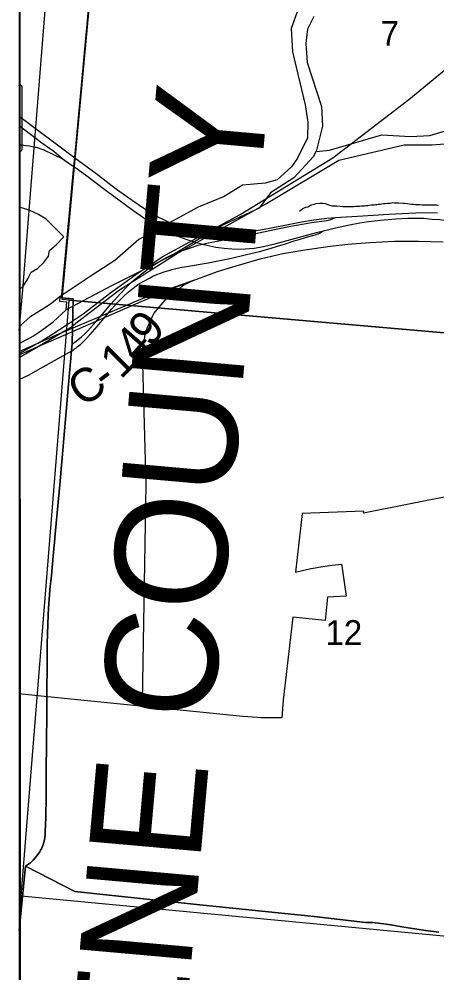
# Model space of a CAD drawing. Extents: x -1.4 to 35.4, y 0 to 22.
# Drawn here: x 24.49 to 25.196, y 14.805 to 16.414 of the extents above; entities that cross this region are included whole.
import ezdxf

# ---------------------------------------------------------------- set-up
doc = ezdxf.new("R2010")
doc.units = 0
for name, color, linetype in [('GM_X_City_Street', 7, 'Continuous'), ('GM_X_County_Road', 7, 'Continuous'), ('GM_X_County_Road_Text', 7, 'Continuous'), ('GM_X_County_Text', 7, 'Continuous'), ('GM_X_Interstate_Shield', 7, 'Continuous'), ('GM_X_Major_River', 7, 'Continuous'), ('GM_X_Minor_Lake', 7, 'Continuous'), ('GM_X_Minor_River', 7, 'Continuous'), ('GM_X_Rail_Line', 7, 'Continuous'), ('GM_X_Section', 7, 'Continuous'), ('GM_X_Section_Text', 7, 'Continuous'), ('GM_X_State_Route', 7, 'Continuous'), ('SC_Scratch1', 7, 'Continuous'), ('SH_Border', 7, 'Continuous'), ('SH_Cut_Line', 7, 'Continuous')]:
    doc.layers.add(name, color=color, linetype=linetype)

msp = doc.modelspace()

# ---------------------------------------------------------------- linework, layer by layer
at = {"layer": 'GM_X_City_Street'}
for p, q in [((24.5666, 16.1759), (24.5826, 16.1649)), ((24.5254, 15.8243), (24.5787, 15.8543))]:
    msp.add_line(p, q, dxfattribs=at)
for points in [[(24.4897, 16.2345), (24.5283, 16.2054), (24.5482, 16.1911), (24.5642, 16.1776), (24.5666, 16.1759)], [(24.4897, 15.8061), (24.5068, 15.8138), (24.5254, 15.8243)]]:
    msp.add_lwpolyline(points, dxfattribs=at)
at = {"layer": 'GM_X_County_Road'}
for points in [[(24.5798, 15.8662), (24.586, 15.8708), (24.5953, 15.8779), (24.6005, 15.8826), (24.6051, 15.8873), (24.6103, 15.893), (24.6155, 15.8987), (24.6339, 15.9199), (24.6449, 15.9329), (24.661, 15.9512), (24.6726, 15.9633), (24.6797, 15.97), (24.6842, 15.9739), (24.696, 15.9837), (24.7073, 15.992), (24.7187, 15.9998), (24.7288, 16.006), (24.7398, 16.012), (24.7478, 16.0161), (24.7547, 16.0191), (24.7642, 16.0229), (24.7774, 16.0276), (24.7922, 16.0324), (24.7994, 16.0341), (24.8097, 16.0366), (24.8384, 16.0422), (24.8762, 16.0495), (24.9212, 16.059), (24.9456, 16.0639), (24.9714, 16.0686), (24.9835, 16.0705), (24.9965, 16.0722), (25.0057, 16.0735), (25.0091, 16.0741), (25.012, 16.0748), (25.0148, 16.0755), (25.0189, 16.0769), (25.0244, 16.0791)], [(24.6898, 15.9653), (24.6906, 15.9659), (24.6991, 15.9711), (24.7109, 15.9773), (24.7159, 15.98), (24.7224, 15.983), (24.7285, 15.9854), (24.7349, 15.9877), (24.7426, 15.99), (24.7475, 15.9914), (24.7546, 15.993), (24.7618, 15.9946), (24.7723, 15.9963), (24.8089, 16.0029), (24.8484, 16.0108), (24.874, 16.0167), (24.8958, 16.0221), (24.914, 16.027), (24.9281, 16.0313), (24.9378, 16.0343), (24.9544, 16.0397), (24.9627, 16.0423), (24.9752, 16.046), (24.9898, 16.05), (24.9933, 16.0511), (24.9952, 16.0518), (24.997, 16.0527), (24.9998, 16.0543), (25.0037, 16.0568)], [(24.6299, 15.9054), (24.6461, 15.9244), (24.6559, 15.9358), (24.6659, 15.9458), (24.6741, 15.9534), (24.6824, 15.9601), (24.6898, 15.9653)], [(24.5787, 15.8543), (24.5814, 15.8559), (24.5834, 15.8574), (24.5856, 15.8589), (24.5879, 15.8607), (24.5932, 15.865), (24.5996, 15.8709), (24.6096, 15.8818), (24.6214, 15.8954), (24.6299, 15.9054)]]:
    msp.add_lwpolyline(points, dxfattribs=at)
msp.add_lwpolyline([(24.4897, 14.8983), (24.4897, 13.9389), (25.4028, 13.8449), (25.498, 14.8392), (24.493, 14.9341)], close=True, dxfattribs=at)
at = {"layer": 'GM_X_County_Text'}
msp.add_lwpolyline([(24.4897, 16.8794), (24.4897, 15.8886), (24.4962, 15.9571), (24.5508, 16.6406), (24.5643, 16.8095), (24.5679, 16.8544), (24.5697, 16.8763), (24.5697, 16.8774), (24.5713, 16.8967), (24.5728, 16.9155), (24.5693, 16.9139)], close=True, dxfattribs=at)
msp.add_lwpolyline([(25.2985, 15.6255), (25.0715, 15.5802), (25.0719, 15.5835), (24.968, 15.5798), (24.9568, 15.481), (24.9828, 15.4872), (24.983, 15.4872), (25.0027, 15.4905), (25.0029, 15.4905), (25.0187, 15.4924), (25.0187, 15.4924), (25.0344, 15.4941), (25.0348, 15.4913), (25.0425, 15.4402), (25.0109, 15.4383), (25.0068, 15.3994), (24.9524, 15.405), (24.9356, 15.2647), (24.9336, 15.2347), (24.8981, 15.2351), (24.8923, 15.2355), (24.8679, 15.2374), (24.5271, 15.2714), (24.4897, 15.2752), (24.4897, 14.0665)], dxfattribs=at)
at = {"layer": 'GM_X_Interstate_Shield'}
msp.add_line((24.4897, 16.3021), (24.4897, 16.1897), dxfattribs=at)
msp.add_lwpolyline([(24.4947, 16.1944), (24.4947, 16.1944), (24.4947, 16.1943), (24.4947, 16.2992)], dxfattribs=at)
for centre, major_axis, start_param, end_param in [((24.3773, 16.5669), (0.3495, 0), 5.039656, 5.042369), ((24.4911, 16.2995), (0.00367, 0), 6.197627, 7.989034), ((24.4939, 16.1867), (0.00568, 0), 1.883976, 2.403227), ((24.4908, 16.1939), (0.00393, 0), 5.054544, 6.418171)]:
    msp.add_ellipse(centre, major_axis=major_axis, ratio=0.8, start_param=start_param, end_param=end_param, dxfattribs=at)
at = {"layer": 'GM_X_Major_River'}
for p, q in [((24.5705, 15.9365), (24.5587, 15.9373)), ((24.5694, 15.9235), (24.5705, 15.9365))]:
    msp.add_line(p, q, dxfattribs=at)
for points in [[(24.9613, 16.4307), (24.9495, 16.3983), (24.9515, 16.3585), (24.9731, 16.2695), (24.9773, 16.2402), (24.977, 16.2136), (24.9602, 16.1792), (24.95, 16.1646), (24.9255, 16.1429), (24.9056, 16.137), (24.8672, 16.1335), (24.8364, 16.1149), (24.792, 16.0964), (24.692, 16.0422), (24.6516, 16.0065), (24.6131, 15.9817), (24.5593, 15.946)], [(24.9876, 16.4182), (24.9772, 16.3972), (24.9739, 16.373), (24.9765, 16.3407), (25.0007, 16.2665), (25.0025, 16.2334), (24.9924, 16.1927), (24.9872, 16.1822), (24.954, 16.1463), (24.9143, 16.1208), (24.8951, 16.0948), (24.8298, 16.0643), (24.7478, 16.0149), (24.6456, 15.9641), (24.5695, 15.9235)], [(24.5593, 15.946), (24.5426, 15.933), (24.5287, 15.9237), (24.5187, 15.9178), (24.5076, 15.9111), (24.4929, 15.8977), (24.4897, 15.8944)], [(24.5587, 15.9373), (24.5593, 15.946)], [(24.4897, 15.8664), (24.4909, 15.8669), (24.5028, 15.8732), (24.514, 15.8798), (24.524, 15.8865), (24.5343, 15.8936), (24.5474, 15.9029), (24.5694, 15.9235)]]:
    msp.add_lwpolyline(points, dxfattribs=at)
at = {"layer": 'GM_X_Minor_Lake'}
for points in [[(24.5652, 16.0464), (24.5356, 16.0765), (24.5228, 16.0843), (24.5077, 16.091), (24.4979, 16.0942), (24.4897, 16.0969)], [(24.4897, 15.9573), (24.497, 15.9641), (24.5044, 15.9758), (24.5103, 15.9871), (24.521, 15.9934), (24.5315, 16.0035), (24.5396, 16.0137), (24.5413, 16.0235), (24.5525, 16.0332), (24.5652, 16.0464)]]:
    msp.add_lwpolyline(points, dxfattribs=at)
at = {"layer": 'GM_X_Minor_River'}
for points in [[(24.9913, 16.1906), (25.0139, 16.1929), (25.1025, 16.2185), (25.151, 16.216), (25.1836, 16.2176), (25.2172, 16.2275)], [(24.9635, 16.0897), (24.9689, 16.0942), (24.9742, 16.0964), (24.9773, 16.0971), (24.983, 16.1004), (24.988, 16.1019), (24.9914, 16.1026), (24.9979, 16.1032), (25.0028, 16.1031), (25.0066, 16.1027), (25.0111, 16.1011), (25.0149, 16.0999), (25.0183, 16.0991), (25.0202, 16.0991), (25.0266, 16.0986), (25.0323, 16.0981), (25.0369, 16.098), (25.0399, 16.098), (25.0422, 16.0976), (25.0441, 16.0975), (25.0464, 16.0975), (25.049, 16.0975), (25.0524, 16.0978), (25.0551, 16.0977), (25.0581, 16.0981), (25.0616, 16.0984), (25.065, 16.0983), (25.068, 16.0987), (25.0707, 16.099), (25.073, 16.099), (25.0756, 16.0993), (25.0787, 16.0996), (25.0817, 16.1), (25.0851, 16.1003), (25.0874, 16.1006), (25.0897, 16.1006), (25.092, 16.1009), (25.0939, 16.1013), (25.0962, 16.1016), (25.0981, 16.1016), (25.1003, 16.1019), (25.1026, 16.1023), (25.1053, 16.1026), (25.1083, 16.103), (25.1118, 16.1033), (25.1159, 16.1036), (25.1186, 16.1039), (25.1213, 16.1043), (25.1239, 16.1042), (25.1266, 16.1042), (25.1285, 16.1041), (25.1311, 16.1041), (25.1383, 16.1032), (25.141, 16.1032), (25.1452, 16.1027), (25.1486, 16.1023), (25.1524, 16.1019), (25.1561, 16.1018), (25.1596, 16.1014), (25.1633, 16.1009), (25.1668, 16.1009), (25.1706, 16.1008), (25.1744, 16.1007), (25.1785, 16.1007), (25.1827, 16.1006), (25.1869, 16.1005), (25.1918, 16.1005), (25.1952, 16.1004), (25.1983, 16.1)]]:
    msp.add_lwpolyline(points, dxfattribs=at)
at = {"layer": 'GM_X_Rail_Line'}
for p, q in [((24.5608, 15.8846), (24.5702, 15.8901)), ((24.5608, 15.8846), (24.5701, 15.8886)), ((24.5216, 15.8671), (24.5608, 15.8846)), ((24.5216, 15.8671), (24.5284, 15.871)), ((24.4897, 15.8497), (24.5216, 15.8671)), ((24.4897, 15.8529), (24.5216, 15.8671)), ((24.4897, 15.8427), (24.5234, 15.8625))]:
    msp.add_line(p, q, dxfattribs=at)
for points in [[(24.5708, 15.8987), (24.5978, 15.9168), (24.6424, 15.9512), (24.687, 15.983), (24.7317, 16.013), (24.863, 16.0843), (25.02, 16.1797), (25.1479, 16.2785), (25.2655, 16.3747), (25.3419, 16.4375), (25.6578, 16.8086), (26.0527, 17.3064), (27.8807, 19.1678), (28.3781, 19.6365)], [(24.5702, 15.8901), (24.5764, 15.8937), (24.5853, 15.9005), (24.5864, 15.9014), (24.6592, 15.9569), (24.7558, 16.0181), (24.9077, 16.1029), (25.0299, 16.1759), (25.1403, 16.2016), (25.1876, 16.2016), (25.2566, 16.2075), (25.3099, 16.2293), (26.5579, 16.8687), (27.4944, 17.3029), (28.0569, 17.523)], [(24.5801, 15.8868), (24.6962, 15.9376), (24.7642, 15.9656), (24.825, 15.9878), (24.8563, 15.9979), (24.8968, 16.0093), (24.9353, 16.0182), (24.9725, 16.0248), (25.0153, 16.0311), (25.0452, 16.0341), (25.0824, 16.0372), (25.1237, 16.039), (25.1642, 16.0393), (25.2063, 16.0379)], [(24.5701, 15.8886), (24.6991, 15.9428), (24.786, 15.9742)], [(24.698, 15.2627), (24.7042, 15.6287), (24.699, 15.8323), (24.7001, 15.8602), (24.7031, 15.8861), (24.7176, 15.9171), (24.7393, 15.9429), (24.7682, 15.9657), (24.786, 15.9742)], [(24.4897, 15.8473), (24.5311, 15.8652), (24.5658, 15.8805), (24.5728, 15.8836), (24.5801, 15.8868)], [(24.5284, 15.871), (24.5453, 15.882), (24.5708, 15.8987)], [(24.5234, 15.8625), (24.5493, 15.8778), (24.5608, 15.8846)]]:
    msp.add_lwpolyline(points, dxfattribs=at)
at = {"layer": 'GM_X_Section'}
for points in [[(25.6685, 16.8528), (25.5769, 15.8524), (24.5744, 15.9398), (24.5624, 15.9411), (24.6573, 16.9582)], [(24.5744, 15.9398), (25.5769, 15.8524), (25.5939, 15.8506), (25.498, 14.8392), (24.493, 14.9341)]]:
    msp.add_lwpolyline(points, close=True, dxfattribs=at)
at = {"layer": 'GM_X_State_Route'}
msp.add_line((24.4897, 16.2502), (24.584, 16.1801), dxfattribs=at)
for points in [[(24.4897, 16.202), (24.4934, 16.202), (24.5068, 16.2003), (24.5174, 16.1978)], [(24.5174, 16.1978), (24.5185, 16.1976), (24.5314, 16.1935), (24.5642, 16.1776)], [(24.584, 16.1801), (24.6193, 16.1538), (24.6545, 16.1272), (24.6808, 16.1083), (24.7002, 16.095), (24.7139, 16.0863), (24.7253, 16.0799), (24.7359, 16.0745), (24.7468, 16.0698), (24.7584, 16.0654), (24.7709, 16.0614), (24.7836, 16.0581), (24.796, 16.0554), (24.8089, 16.0533), (24.8207, 16.0522), (24.8349, 16.0516), (24.849, 16.052), (24.857, 16.0526), (24.8635, 16.0532), (24.8795, 16.0553), (24.901, 16.059), (24.9357, 16.0658), (24.9668, 16.0717), (24.9877, 16.075), (25.0098, 16.0778), (25.0244, 16.0791), (25.0327, 16.0799), (25.0612, 16.0817), (25.1145, 16.0848), (25.148, 16.0867), (25.1716, 16.0874), (25.1964, 16.0872)], [(24.5826, 16.1649), (24.5855, 16.1631), (24.6021, 16.151), (24.6369, 16.125), (24.6819, 16.0918), (24.7002, 16.0789), (24.7142, 16.0698), (24.726, 16.063), (24.7369, 16.0572), (24.7498, 16.0511), (24.7635, 16.0454), (24.7763, 16.0408), (24.7911, 16.0362), (24.7994, 16.0341), (24.8067, 16.0323), (24.8219, 16.0292), (24.836, 16.0272), (24.849, 16.0261), (24.8588, 16.0257), (24.8718, 16.0261), (24.8866, 16.0276), (24.9024, 16.0305), (24.9241, 16.0356), (24.9919, 16.0539), (25.0037, 16.0568), (25.024, 16.0618), (25.0476, 16.067), (25.0654, 16.0703), (25.0802, 16.0726), (25.1, 16.0748), (25.1254, 16.0768), (25.1465, 16.078), (25.1609, 16.0782), (25.1727, 16.0778), (25.1876, 16.0766)], [(25.1876, 16.0766), (25.2006, 16.0756), (25.2038, 16.0753), (25.2139, 16.0745), (25.2335, 16.0726), (25.2449, 16.0712), (25.2578, 16.0694), (25.2876, 16.0648), (25.3293, 16.0577), (25.3665, 16.0505), (25.3957, 16.0444), (25.4145, 16.04), (25.4307, 16.0358), (25.4619, 16.0271), (25.4922, 16.0178), (25.5508, 15.9988), (25.6139, 15.978), (25.7158, 15.9443), (25.7651, 15.9281), (25.8967, 15.8847), (25.9623, 15.8633), (26.153, 15.8005), (26.237, 15.7729)]]:
    msp.add_lwpolyline(points, dxfattribs=at)
at = {"layer": 'SC_Scratch1'}
for points in [[(24.4897, 19.8546), (24.4897, 14.8759), (24.5008, 14.9848), (24.5054, 14.9878), (24.5082, 14.9899), (24.5101, 14.9916), (24.5134, 14.9947), (24.517, 14.9986), (24.5197, 15.0021), (24.5226, 15.006), (24.5246, 15.009), (24.5253, 15.0102), (24.5261, 15.0117), (24.5274, 15.0141), (24.5297, 15.0195), (24.532, 15.0269), (24.5331, 15.0324), (24.5336, 15.0373), (24.5339, 15.0431), (24.5343, 15.0542), (24.5347, 15.0672), (24.5352, 15.1015), (24.5353, 15.1113), (24.5353, 15.1393), (24.5358, 15.1971), (24.5365, 15.2387), (24.5365, 15.246), (24.5368, 15.2829), (24.5371, 15.3207), (24.5374, 15.3599), (24.5387, 15.4086), (24.5394, 15.42), (24.5411, 15.4417), (24.5419, 15.4515), (24.5442, 15.475), (24.5448, 15.4816), (24.5491, 15.527), (24.5493, 15.5299), (24.5502, 15.5392), (24.5563, 15.6043), (24.5583, 15.628), (24.5733, 15.7976), (24.5785, 15.8548), (24.5796, 15.8668), (24.581, 15.9418), (24.5616, 15.9439), (24.5823, 16.1654), (24.5837, 16.1806), (24.6203, 16.5765)], [(24.6203, 16.5765), (24.5837, 16.1806), (24.5823, 16.1654), (24.5616, 15.9439), (24.581, 15.9418), (24.5796, 15.8668), (24.5785, 15.8548), (24.5733, 15.7976), (24.5583, 15.628), (24.5563, 15.6043), (24.5502, 15.5392), (24.5493, 15.5299), (24.5491, 15.527), (24.5448, 15.4816), (24.5442, 15.475), (24.5419, 15.4515), (24.5411, 15.4417), (24.5394, 15.42), (24.5387, 15.4086), (24.5374, 15.3599), (24.5371, 15.3207), (24.5368, 15.2829), (24.5365, 15.246), (24.5365, 15.2387), (24.5358, 15.1971), (24.5353, 15.1393), (24.5353, 15.1113), (24.5352, 15.1015), (24.5347, 15.0672), (24.5343, 15.0542), (24.5339, 15.0431), (24.5336, 15.0373), (24.5331, 15.0324), (24.532, 15.0269), (24.5297, 15.0195), (24.5274, 15.0141), (24.5261, 15.0117), (24.5253, 15.0102), (24.5246, 15.009), (24.5226, 15.006), (24.5197, 15.0021), (24.517, 14.9986), (24.5134, 14.9947), (24.5101, 14.9916), (24.5082, 14.9899), (24.5054, 14.9878), (24.5008, 14.9848), (24.5837, 14.9418), (24.7951, 14.9197), (24.9881, 14.8997), (25.0749, 14.8895), (25.0759, 14.8896), (25.0834, 14.8897), (25.0873, 14.8895), (25.0915, 14.8892), (25.1057, 14.8873), (25.121, 14.885), (25.1399, 14.8819), (25.1582, 14.8789), (25.176, 14.8761), (25.199, 14.8731)], [(25.199, 14.8731), (25.176, 14.8761), (25.1582, 14.8789), (25.1399, 14.8819), (25.121, 14.885), (25.1057, 14.8873), (25.0915, 14.8892), (25.0873, 14.8895), (25.0834, 14.8897), (25.0759, 14.8896), (25.0749, 14.8895), (24.9881, 14.8997), (24.7951, 14.9197), (24.5837, 14.9418), (24.5008, 14.9848), (24.4897, 14.8759), (24.4897, 13.0546)]]:
    msp.add_lwpolyline(points, dxfattribs=at)
at = {"layer": 'SH_Border'}
msp.add_lwpolyline([(24.4897, 19.8546), (24.4921, 13.0546), (31.2897, 13.0546), (31.2897, 19.8546)], close=True, dxfattribs=at)
at = {"layer": 'SH_Cut_Line'}
for points in [[(24.4897, 19.8546), (24.4897, 14.8759), (24.5008, 14.9848), (24.5054, 14.9878), (24.5082, 14.9899), (24.5101, 14.9916), (24.5134, 14.9947), (24.517, 14.9986), (24.5197, 15.0021), (24.5226, 15.006), (24.5246, 15.009), (24.5253, 15.0102), (24.5261, 15.0117), (24.5274, 15.0141), (24.5297, 15.0195), (24.532, 15.0269), (24.5331, 15.0324), (24.5336, 15.0373), (24.5339, 15.0431), (24.5343, 15.0542), (24.5347, 15.0672), (24.5352, 15.1015), (24.5353, 15.1113), (24.5353, 15.1393), (24.5358, 15.1971), (24.5365, 15.2387), (24.5365, 15.246), (24.5368, 15.2829), (24.5371, 15.3207), (24.5374, 15.3599), (24.5387, 15.4086), (24.5394, 15.42), (24.5411, 15.4417), (24.5419, 15.4515), (24.5442, 15.475), (24.5448, 15.4816), (24.5491, 15.527), (24.5493, 15.5299), (24.5502, 15.5392), (24.5563, 15.6043), (24.5583, 15.628), (24.5733, 15.7976), (24.5785, 15.8548), (24.5796, 15.8668), (24.581, 15.9418), (24.5616, 15.9439), (24.5823, 16.1654), (24.5837, 16.1806), (24.6203, 16.5765)], [(24.6203, 16.5765), (24.5837, 16.1806), (24.5823, 16.1654), (24.5616, 15.9439), (24.581, 15.9418), (24.5796, 15.8668), (24.5785, 15.8548), (24.5733, 15.7976), (24.5583, 15.628), (24.5563, 15.6043), (24.5502, 15.5392), (24.5493, 15.5299), (24.5491, 15.527), (24.5448, 15.4816), (24.5442, 15.475), (24.5419, 15.4515), (24.5411, 15.4417), (24.5394, 15.42), (24.5387, 15.4086), (24.5374, 15.3599), (24.5371, 15.3207), (24.5368, 15.2829), (24.5365, 15.246), (24.5365, 15.2387), (24.5358, 15.1971), (24.5353, 15.1393), (24.5353, 15.1113), (24.5352, 15.1015), (24.5347, 15.0672), (24.5343, 15.0542), (24.5339, 15.0431), (24.5336, 15.0373), (24.5331, 15.0324), (24.532, 15.0269), (24.5297, 15.0195), (24.5274, 15.0141), (24.5261, 15.0117), (24.5253, 15.0102), (24.5246, 15.009), (24.5226, 15.006), (24.5197, 15.0021), (24.517, 14.9986), (24.5134, 14.9947), (24.5101, 14.9916), (24.5082, 14.9899), (24.5054, 14.9878), (24.5008, 14.9848), (24.4897, 14.8759), (24.4897, 13.0546)]]:
    msp.add_lwpolyline(points, dxfattribs=at)

# ---------------------------------------------------------------- texts
at = {"layer": 'GM_X_County_Road_Text'}
for s, rotation, p in [('9', 48.6258, (24.7118, 15.8588)), ('4', 49.0718, (24.6891, 15.8327)), ('1', 44.997, (24.6616, 15.8049)), ('C', 35.7629, (24.5979, 15.7574)), ('-', 37.2125, (24.6368, 15.7854))]:
    msp.add_text(s, height=0.0568, rotation=rotation, dxfattribs=at).set_placement(p)
at = {"layer": 'GM_X_County_Text'}
msp.add_text('GREENE COUNTY', height=0.189394, rotation=84.9155, dxfattribs=at).set_placement((24.7155, 14.0917))
at = {"layer": 'GM_X_Section_Text'}
for s, height, p in [('7', 0.0419, (25.1005, 16.3689)), ('12', 0.04186, (25.0071, 15.3579))]:
    msp.add_text(s, height=height, rotation=0, dxfattribs=at).set_placement(p)

doc.saveas('drawing.dxf')
